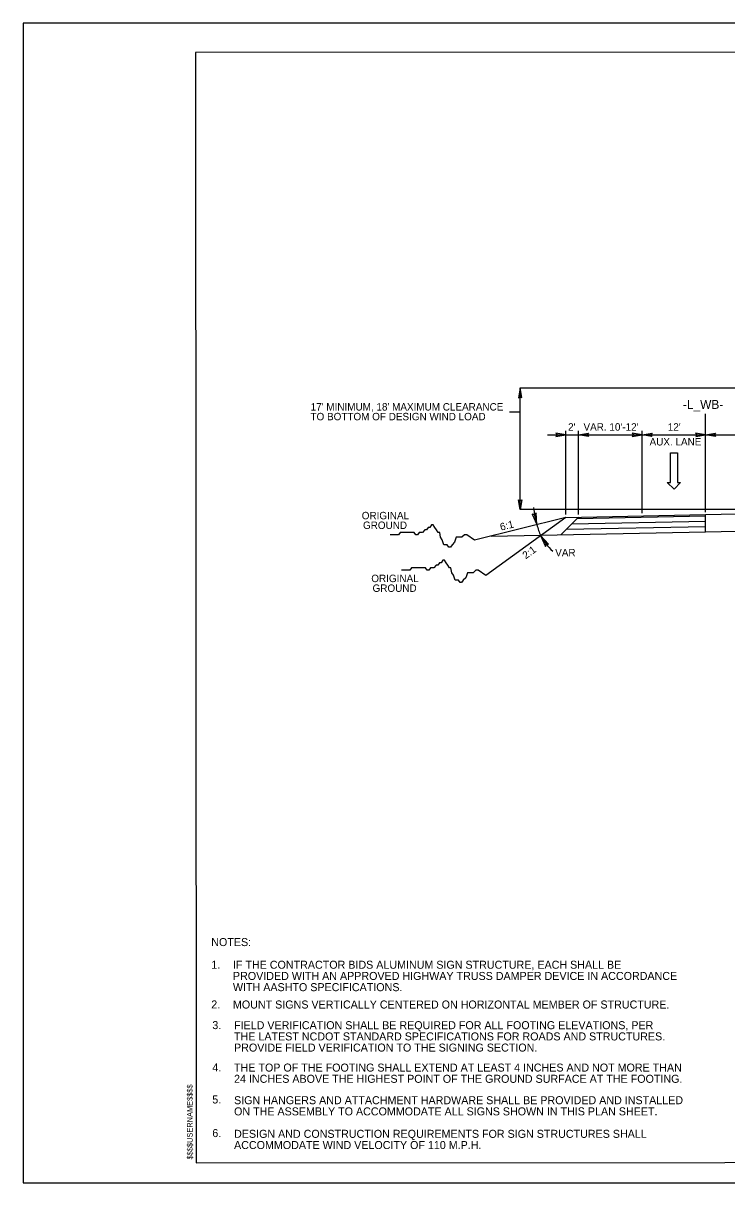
# Model space of a CAD drawing. Extents: x 1727387 to 1728895, y 539219 to 540208.
# Drawn here: x 1727387.3 to 1727520.2, y 539369.8 to 539589 of the extents above; entities that cross this region are included whole.
import ezdxf

# ---------------------------------------------------------------- set-up
doc = ezdxf.new("R2010")
doc.units = 0
for name, color, linetype in [('Default', 7, 'Continuous'), ('DEV BORDER CELL', 7, 'Continuous'), ('Overhead Sheet Border', 7, 'Continuous'), ('Overhead Sheet Text', 7, 'Continuous'), ('Prop Dimension Text', 7, 'Continuous'), ('Sheet Plot Border Outside CELL', 7, 'Continuous'), ('Typical Hinge Slope Interstate CELL', 7, 'Continuous'), ('Typical Pavement Slope CELL', 7, 'Continuous'), ('Typical Pavement Slope Information CELL', 7, 'Continuous'), ('Typical Text Centerline CELL', 7, 'Continuous')]:
    doc.layers.add(name, color=color, linetype=linetype)

msp = doc.modelspace()

# ---------------------------------------------------------------- linework, layer by layer
at = {"layer": 'Default'}
for p, q in [((1727481.19, 539520.12), (1727608.75, 539520.12)), ((1727481.19, 539497.08), (1727481.19, 539520.12)), ((1727481.19, 539515.52), (1727479.19, 539515.52)), ((1727516.23, 539496.63), (1727516.23, 539515.21)), ((1727489.81, 539496.15), (1727489.81, 539511.95)), ((1727492.21, 539496.15), (1727492.21, 539511.95)), ((1727492.21, 539496.15), (1727492.21, 539511.71)), ((1727504.22, 539496.39), (1727504.22, 539511.95)), ((1727516.23, 539496.63), (1727516.23, 539511.95)), ((1727486.36, 539511.21), (1727492.24, 539511.21)), ((1727492.24, 539511.21), (1727504.25, 539511.21)), ((1727504.25, 539511.21), (1727516.25, 539511.21)), ((1727516.25, 539511.21), (1727528.26, 539511.21)), ((1727509.6, 539502.23), (1727509.6, 539507.83)), ((1727509.6, 539507.83), (1727510.92, 539507.83)), ((1727510.92, 539507.83), (1727510.92, 539502.23)), ((1727510.28, 539500.97), (1727509, 539502.23)), ((1727509, 539502.23), (1727509.6, 539502.23)), ((1727511.52, 539502.23), (1727510.28, 539500.97)), ((1727510.92, 539502.23), (1727511.52, 539502.23)), ((1727653.65, 539497.08), (1727481.19, 539497.08))]:
    msp.add_line(p, q, dxfattribs=at)
for points in [[(1727481.51, 539518.25), (1727481.19, 539520.13), (1727480.86, 539518.24), (1727481.19, 539518.48)], [(1727487.94, 539510.89), (1727489.81, 539511.21), (1727487.93, 539511.54), (1727488.17, 539511.21)], [(1727494.09, 539510.89), (1727492.21, 539511.21), (1727494.1, 539511.54), (1727493.86, 539511.21)], [(1727502.35, 539510.89), (1727504.22, 539511.21), (1727502.34, 539511.54), (1727502.58, 539511.21)], [(1727506.1, 539510.89), (1727504.22, 539511.21), (1727506.11, 539511.54), (1727505.87, 539511.21)], [(1727514.36, 539510.89), (1727516.23, 539511.21), (1727514.35, 539511.54), (1727514.59, 539511.21)], [(1727518.11, 539510.89), (1727516.23, 539511.21), (1727518.12, 539511.54), (1727517.88, 539511.21)], [(1727481.51, 539498.95), (1727481.19, 539497.08), (1727480.86, 539498.96), (1727481.19, 539498.72)], [(1727483.46, 539496.25), (1727484.35, 539494.25), (1727484.19, 539496.45), (1727483.89, 539496.09)], [(1727486.57, 539490.56), (1727485.06, 539492.16), (1727485.95, 539490.13), (1727486.11, 539490.58)], [(1727486.57, 539490.56), (1727485.06, 539492.16), (1727485.95, 539490.13), (1727486.11, 539490.58)]]:
    msp.add_lwpolyline(points, close=True, dxfattribs=at)
at = {"layer": 'DEV BORDER CELL'}
msp.add_line((1727387.25, 539589.02), (1727387.25, 539589.02), dxfattribs=at)
at = {"layer": 'Overhead Sheet Border'}
msp.add_lwpolyline([(1727719.57, 539583.63), (1727419.83, 539583.47), (1727419.94, 539373.65), (1727719.68, 539373.81)], close=True, dxfattribs=at)
at = {"layer": 'Sheet Plot Border Outside CELL'}
msp.add_lwpolyline([(1727723.82, 539589.02), (1727387.25, 539589.02), (1727387.25, 539369.85), (1727723.82, 539369.85)], close=True, dxfattribs=at)
at = {"layer": 'Typical Hinge Slope Interstate CELL'}
for points in [[(1727472.57, 539491.3), (1727471.13, 539492.31), (1727470.66, 539492.31), (1727470.19, 539491.85), (1727469.88, 539491.85), (1727469.41, 539491.85), (1727469.1, 539491.85), (1727468.79, 539490.91), (1727468.32, 539490.45), (1727468.01, 539489.98), (1727467.7, 539489.98), (1727467.39, 539490.45), (1727467.08, 539490.45), (1727466.77, 539490.45), (1727466.45, 539491.38), (1727466.14, 539491.85), (1727465.99, 539492.78), (1727465.68, 539492.78), (1727465.36, 539493.25), (1727465.05, 539493.72), (1727464.74, 539494.19), (1727464.43, 539494.19), (1727464.12, 539493.72), (1727463.81, 539493.72), (1727463.5, 539493.25), (1727463.18, 539493.25), (1727462.72, 539492.78), (1727462.4, 539492.78), (1727462.09, 539492.78), (1727461.78, 539492.31), (1727461.47, 539492.31), (1727461.16, 539492.78), (1727460.85, 539492.78), (1727460.54, 539492.78), (1727460.22, 539492.78), (1727459.91, 539492.78), (1727459.45, 539492.78), (1727458.98, 539492.78), (1727458.51, 539492.78), (1727458.2, 539492.31), (1727457.73, 539492.31), (1727457.27, 539492.31), (1727456.64, 539492.31)], [(1727474.69, 539484.61), (1727473.25, 539485.63), (1727472.78, 539485.63), (1727472.31, 539485.16), (1727472, 539485.16), (1727471.54, 539485.16), (1727471.22, 539485.16), (1727470.91, 539484.22), (1727470.44, 539483.76), (1727470.13, 539483.29), (1727469.82, 539483.29), (1727469.51, 539483.76), (1727469.2, 539483.76), (1727468.89, 539483.76), (1727468.58, 539484.69), (1727468.26, 539485.16), (1727468.11, 539486.1), (1727467.8, 539486.1), (1727467.49, 539486.56), (1727467.17, 539487.03), (1727466.86, 539487.5), (1727466.55, 539487.5), (1727466.24, 539487.03), (1727465.93, 539487.03), (1727465.62, 539486.56), (1727465.31, 539486.56), (1727464.84, 539486.1), (1727464.53, 539486.1), (1727464.21, 539486.1), (1727463.9, 539485.63), (1727463.59, 539485.63), (1727463.28, 539486.1), (1727462.97, 539486.1), (1727462.66, 539486.1), (1727462.35, 539486.1), (1727462.03, 539486.1), (1727461.57, 539486.1), (1727461.1, 539486.1), (1727460.63, 539486.1), (1727460.32, 539485.63), (1727459.85, 539485.63), (1727459.39, 539485.63), (1727458.76, 539485.63)]]:
    msp.add_lwpolyline(points, dxfattribs=at)
for centre, start, end in [((1727495.79, 539498.11), 182.9343, 198.686), ((1727495.61, 539498.02), 209.0778, 226.6941), ((1727495.61, 539498.02), 209.0778, 226.6941)]:
    msp.add_arc(centre, 12.07, start, end, dxfattribs=at)
msp.add_ellipse((1727490.13, 539501.13), major_axis=(-1.85, -11.93), ratio=0.5, start_param=5.403228, end_param=5.638322, dxfattribs=at)
at = {"layer": 'Typical Pavement Slope CELL'}
for p, q in [((1727489.81, 539495.61), (1727516.23, 539496.14)), ((1727491.96, 539495.4), (1727516.23, 539495.89)), ((1727516.23, 539496.14), (1727563.08, 539497.08)), ((1727516.23, 539492.89), (1727516.23, 539496.14)), ((1727489.81, 539495.61), (1727472.57, 539491.3)), ((1727489.81, 539495.61), (1727474.69, 539484.61)), ((1727492.21, 539495.66), (1727488.9, 539492.34)), ((1727489.92, 539493.36), (1727516.23, 539493.89)), ((1727490.94, 539494.38), (1727516.23, 539494.89)), ((1727516.23, 539492.89), (1727563.08, 539493.83)), ((1727475.68, 539492.08), (1727516.23, 539492.89))]:
    msp.add_line(p, q, dxfattribs=at)

# ---------------------------------------------------------------- texts
at = {"layer": 'Overhead Sheet Text'}
for s, height, p in [('NOTES:', 1.513, (1727422.8, 539414.59)), ('1.', 1.513, (1727422.8, 539410.31)), ('IF THE CONTRACTOR BIDS ALUMINUM SIGN STRUCTURE, EACH SHALL BE ', 1.5128, (1727426.9, 539410.31)), ('PROVIDED WITH AN APPROVED HIGHWAY TRUSS DAMPER DEVICE IN ACCORDANCE', 1.5128, (1727426.9, 539408.19)), ('WITH AASHTO SPECIFICATIONS.', 1.5128, (1727426.9, 539406.07)), ('2.', 1.513, (1727422.8, 539402.81)), ('MOUNT SIGNS VERTICALLY CENTERED ON HORIZONTAL MEMBER OF STRUCTURE.', 1.5128, (1727426.9, 539402.79)), ('3.', 1.513, (1727423, 539398.9)), ('FIELD VERIFICATION SHALL BE REQUIRED FOR ALL FOOTING ELEVATIONS, PER', 1.5128, (1727427.11, 539398.88)), ('THE LATEST NCDOT STANDARD SPECIFICATIONS FOR ROADS AND STRUCTURES.', 1.5128, (1727427.11, 539396.76)), ('PROVIDE FIELD VERIFICATION TO THE SIGNING SECTION.', 1.5128, (1727427.11, 539394.65)), ('4.', 1.513, (1727423, 539390.89)), ('THE TOP OF THE FOOTING SHALL EXTEND AT LEAST 4 INCHES AND NOT MORE THAN', 1.5128, (1727427.11, 539390.87)), ('24 INCHES ABOVE THE HIGHEST POINT OF THE GROUND SURFACE AT THE FOOTING.', 1.5128, (1727427.11, 539388.75)), ('5.', 1.513, (1727423, 539384.84)), ('SIGN HANGERS AND ATTACHMENT HARDWARE SHALL BE PROVIDED AND INSTALLED ', 1.5128, (1727427.11, 539384.7)), ('ON THE ASSEMBLY TO ACCOMMODATE ALL SIGNS SHOWN IN THIS PLAN SHEET.', 1.5128, (1727427.11, 539382.59)), ('6.', 1.513, (1727423, 539378.49)), ('DESIGN AND CONSTRUCTION REQUIREMENTS FOR SIGN STRUCTURES SHALL', 1.5128, (1727427.11, 539378.35)), ('ACCOMMODATE WIND VELOCITY OF 110 M.P.H.', 1.5128, (1727427.11, 539376.23))]:
    msp.add_text(s, height=height, dxfattribs=at).set_placement(p)
msp.add_text('$$$$USERNAME$$$$', height=1.0491, rotation=90.0308, dxfattribs=at).set_placement((1727419.28, 539374.26))
at = {"layer": 'Prop Dimension Text'}
for s, p in [("17' MINIMUM, 18' MAXIMUM CLEARANCE", (1727441.59, 539515.81)), ('TO BOTTOM OF DESIGN WIND LOAD', (1727441.56, 539513.97)), ('ORIGINAL', (1727451.24, 539495.26)), ('GROUND', (1727451.48, 539493.43)), ('VAR', (1727487.81, 539488.25)), ('ORIGINAL', (1727453.05, 539483.38)), ('GROUND', (1727453.29, 539481.54))]:
    msp.add_text(s, height=1.401, dxfattribs=at).set_placement(p)
for s, rotation, p in [('6:1', 14.0362, (1727477.57, 539493.09)), ('2:1', 36.0298, (1727482.25, 539487.68))]:
    msp.add_text(s, height=1.401, rotation=rotation, dxfattribs=at).set_placement(p)
at = {"layer": 'Typical Pavement Slope Information CELL'}
for s, p in [("2'", (1727490.24, 539512.01)), ("VAR. 10'-12'", (1727493.16, 539512.01)), ("12'", (1727509.09, 539512.01)), ('AUX. LANE', (1727505.65, 539509.21))]:
    msp.add_text(s, height=1.401, dxfattribs=at).set_placement(p)
at = {"layer": 'Typical Text Centerline CELL'}
msp.add_text('-L_WB-', height=1.684, dxfattribs=at).set_placement((1727511.95, 539516.12))

doc.saveas('drawing.dxf')
